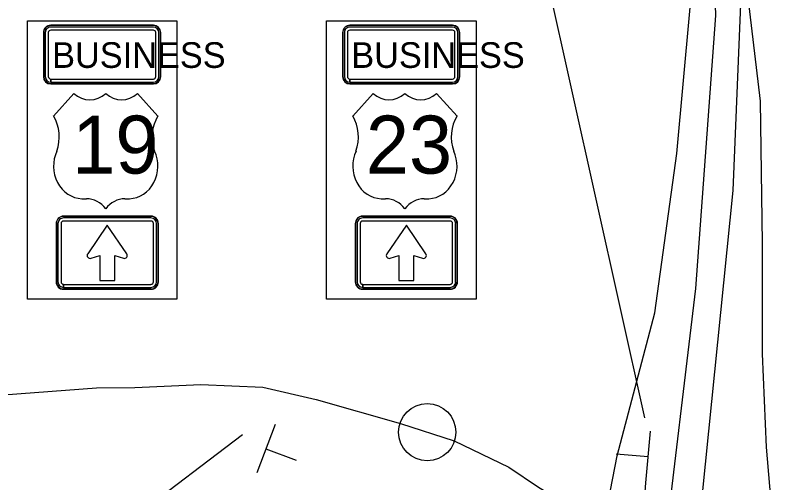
# Model space of a CAD drawing. Extents: x 886234 to 968767, y 455416 to 684046.
# Drawn here: x 914018 to 916508, y 470126 to 471656 of the extents above; entities that cross this region are included whole.
import ezdxf

# ---------------------------------------------------------------- set-up
doc = ezdxf.new("R2010")
doc.units = 0
for name, color, linetype in [('TC DEV SIGN', 7, 'Continuous'), ('TC DEV SIGN BLACK 239', 7, 'Continuous'), ('TC DEV SIGN BLACK ZERO', 7, 'Continuous'), ('TC DEV SIGN WHITE', 7, 'Continuous'), ('TC LABEL TEXT', 7, 'Continuous')]:
    doc.layers.add(name, color=color, linetype=linetype)

msp = doc.modelspace()

# ---------------------------------------------------------------- linework, layer by layer
at = {"layer": 'TC DEV SIGN'}
for p, q in [((914868.7, 470316.7), (914808.4, 470157.9)), ((916083, 470125.8), (916097.8, 470295)), ((914838.6, 470237.3), (914937, 470199.9)), ((916090.4, 470210.4), (915985.5, 470219.6)), ((916068.2, 469956.7), (916083, 470125.8))]:
    msp.add_line(p, q, dxfattribs=at)
at = {"layer": 'TC DEV SIGN BLACK 239'}
for p, q in [((914469.9, 471617), (914133.9, 471617)), ((915449.4, 471617), (915113.4, 471617)), ((914115.9, 471599), (914115.9, 471455)), ((914125.9, 471599), (914125.9, 471455)), ((914469.9, 471607), (914133.9, 471607)), ((914477.9, 471455), (914477.9, 471599)), ((914487.9, 471455), (914487.9, 471599)), ((915095.4, 471599), (915095.4, 471455)), ((915105.4, 471599), (915105.4, 471455)), ((915449.4, 471607), (915113.4, 471607)), ((915457.4, 471455), (915457.4, 471599)), ((915467.4, 471455), (915467.4, 471599)), ((914133.9, 471437), (914133.9, 471447)), ((914134, 471447), (914469.9, 471447)), ((914134, 471447), (914134, 471437)), ((914134, 471437), (914469.9, 471437)), ((915113.4, 471437), (915113.4, 471447)), ((915113.5, 471447), (915449.4, 471447)), ((915113.5, 471447), (915113.5, 471437)), ((915113.5, 471437), (915449.4, 471437)), ((914462.1, 470992.3), (914175.8, 470992.3)), ((915441.6, 470992.3), (915155.3, 470992.3)), ((914157.6, 470974.1), (914157.6, 470783.3)), ((914167.7, 470974.1), (914167.7, 470783.3)), ((914462.1, 470982.2), (914175.8, 470982.2)), ((914470.2, 470783.3), (914470.2, 470974.1)), ((914480.3, 470783.3), (914480.3, 470974.1)), ((915137.1, 470974.1), (915137.1, 470783.3)), ((915147.2, 470974.1), (915147.2, 470783.3)), ((915441.6, 470982.2), (915155.3, 470982.2)), ((915449.7, 470783.3), (915449.7, 470974.1)), ((915459.8, 470783.3), (915459.8, 470974.1)), ((914175.8, 470765), (914175.8, 470775.1)), ((914175.9, 470775.1), (914462.1, 470775.1)), ((914175.9, 470775.1), (914175.9, 470765)), ((914175.9, 470765), (914462.1, 470765)), ((915155.3, 470765), (915155.3, 470775.1)), ((915155.4, 470775.1), (915441.6, 470775.1)), ((915155.4, 470775.1), (915155.4, 470765)), ((915155.4, 470765), (915441.6, 470765))]:
    msp.add_line(p, q, dxfattribs=at)
for points in [[(914383, 470875.3), (914318.9, 470968.6), (914254.9, 470875.3)], [(914383, 470875.3), (914318.9, 470968.6), (914254.9, 470875.3)], [(914383, 470875.3), (914318.9, 470968.6), (914254.9, 470875.3)], [(915362.5, 470875.3), (915298.4, 470968.6), (915234.4, 470875.3)], [(915362.5, 470875.3), (915298.4, 470968.6), (915234.4, 470875.3)], [(915362.5, 470875.3), (915298.4, 470968.6), (915234.4, 470875.3)], [(914265.9, 470860.5), (914294.6, 470869.5), (914294.6, 470787.7), (914343.3, 470787.7)], [(914265.9, 470860.5), (914294.6, 470869.5), (914294.6, 470787.7), (914343.3, 470787.7)], [(914265.9, 470860.5), (914294.6, 470869.5), (914294.6, 470787.7), (914343.3, 470787.7)], [(914343.3, 470787.7), (914343.3, 470869.5), (914372, 470860.5)], [(914343.3, 470787.7), (914343.3, 470869.5), (914372, 470860.5)], [(914343.3, 470787.7), (914343.3, 470869.5), (914372, 470860.5)], [(915245.4, 470860.5), (915274.1, 470869.5), (915274.1, 470787.7), (915322.8, 470787.7)], [(915245.4, 470860.5), (915274.1, 470869.5), (915274.1, 470787.7), (915322.8, 470787.7)], [(915245.4, 470860.5), (915274.1, 470869.5), (915274.1, 470787.7), (915322.8, 470787.7)], [(915322.8, 470787.7), (915322.8, 470869.5), (915351.5, 470860.5)], [(915322.8, 470787.7), (915322.8, 470869.5), (915351.5, 470860.5)], [(915322.8, 470787.7), (915322.8, 470869.5), (915351.5, 470860.5)]]:
    msp.add_lwpolyline(points, dxfattribs=at)
for centre, start, end in [((914262.9, 470869.7), 145.5508, 287.601), ((914262.9, 470869.7), 145.5508, 287.601), ((914262.9, 470869.7), 145.5508, 287.601), ((914374.9, 470869.7), 252.399, 34.4492), ((914374.9, 470869.7), 252.399, 34.4492), ((914374.9, 470869.7), 252.399, 34.4492), ((915242.5, 470869.7), 145.5508, 287.601), ((915242.5, 470869.7), 145.5508, 287.601), ((915242.5, 470869.7), 145.5508, 287.601), ((915354.4, 470869.7), 252.399, 34.4492), ((915354.4, 470869.7), 252.399, 34.4492), ((915354.4, 470869.7), 252.399, 34.4492)]:
    msp.add_arc(centre, 9.74, start, end, dxfattribs=at)
for centre, major_axis, start_param, end_param in [((914133.9, 471599), (18, 0), 1.570796, 3.141593), ((914469.9, 471599), (18, 0), 0, 1.570796), ((915113.4, 471599), (18, 0), 1.570796, 3.141593), ((915449.4, 471599), (18, 0), 0, 1.570796), ((914133.9, 471599), (8, 0), 1.570796, 3.141593), ((914469.9, 471599), (8, 0), 0, 1.570796), ((915113.4, 471599), (8, 0), 1.570796, 3.141593), ((915449.4, 471599), (8, 0), 0, 1.570796), ((914133.9, 471455), (18, 0), 3.141593, 4.712389), ((914133.9, 471455), (8, 0), 3.141593, 4.712389), ((914469.9, 471455), (18, 0), 4.712389, 6.283185), ((914469.9, 471455), (8, 0), 4.712389, 6.283185), ((915113.4, 471455), (18, 0), 3.141593, 4.712389), ((915113.4, 471455), (8, 0), 3.141593, 4.712389), ((915449.4, 471455), (18, 0), 4.712389, 6.283185), ((915449.4, 471455), (8, 0), 4.712389, 6.283185), ((914175.8, 470974.1), (18.3, 0), 1.570796, 3.141593), ((914462.1, 470974.1), (18.3, 0), 0, 1.570796), ((915155.3, 470974.1), (18.3, 0), 1.570796, 3.141593), ((915441.6, 470974.1), (18.3, 0), 0, 1.570796), ((914175.8, 470974.1), (8.11, 0), 1.570796, 3.141593), ((914462.1, 470974.1), (8.11, 0), 0, 1.570796), ((915155.3, 470974.1), (8.11, 0), 1.570796, 3.141593), ((915441.6, 470974.1), (8.11, 0), 0, 1.570796), ((914175.8, 470783.3), (18.3, 0), 3.141593, 4.712389), ((914175.8, 470783.3), (8.11, 0), 3.141593, 4.712389), ((914462.1, 470783.3), (18.3, 0), 4.712389, 6.283185), ((914462.1, 470783.3), (8.11, 0), 4.712389, 6.283185), ((915155.3, 470783.3), (18.3, 0), 3.141593, 4.712389), ((915155.3, 470783.3), (8.11, 0), 3.141593, 4.712389), ((915441.6, 470783.3), (18.3, 0), 4.712389, 6.283185), ((915441.6, 470783.3), (8.11, 0), 4.712389, 6.283185)]:
    msp.add_ellipse(centre, major_axis=major_axis, ratio=0.999865, start_param=start_param, end_param=end_param, dxfattribs=at)
at = {"layer": 'TC DEV SIGN BLACK ZERO'}
for p, q in [((914469.9, 471623), (914133.9, 471623)), ((914133.9, 471622), (914133.9, 471622)), ((914469.9, 471622), (914133.9, 471622)), ((914469.9, 471622), (914469.9, 471622)), ((915449.4, 471623), (915113.4, 471623)), ((915113.4, 471622), (915113.4, 471622)), ((915449.4, 471622), (915113.4, 471622)), ((915449.4, 471622), (915449.4, 471622)), ((914109.9, 471599), (914109.9, 471455)), ((914110.9, 471599), (914110.9, 471455)), ((914110.9, 471599), (914110.9, 471599)), ((914492.9, 471599), (914492.9, 471599)), ((914492.9, 471455), (914492.9, 471599)), ((914493.9, 471455), (914493.9, 471599)), ((915089.4, 471599), (915089.4, 471455)), ((915090.4, 471599), (915090.4, 471455)), ((915090.4, 471599), (915090.4, 471599)), ((915472.4, 471599), (915472.4, 471599)), ((915472.4, 471455), (915472.4, 471599)), ((915473.4, 471455), (915473.4, 471599)), ((914110.9, 471455), (914110.9, 471455)), ((914492.9, 471455), (914492.9, 471455)), ((915090.4, 471455), (915090.4, 471455)), ((915472.4, 471455), (915472.4, 471455)), ((914133.9, 471431), (914133.9, 471432)), ((914133.9, 471432), (914133.9, 471432)), ((914133.9, 471432), (914469.9, 471432)), ((914133.9, 471432), (914133.9, 471431)), ((914133.9, 471431), (914469.9, 471431)), ((914469.9, 471432), (914469.9, 471432)), ((915113.4, 471431), (915113.4, 471432)), ((915113.4, 471432), (915113.4, 471432)), ((915113.4, 471432), (915449.4, 471432)), ((915113.4, 471432), (915113.4, 471431)), ((915113.4, 471431), (915449.4, 471431)), ((915449.4, 471432), (915449.4, 471432)), ((914143.2, 471326), (914210, 471399.8)), ((914143.2, 471326), (914210, 471399.8)), ((914418, 471399.8), (914484.8, 471326)), ((914418, 471399.8), (914484.8, 471326)), ((915122.7, 471326), (915189.5, 471399.8)), ((915122.7, 471326), (915189.5, 471399.8)), ((915397.5, 471399.8), (915464.3, 471326)), ((915397.5, 471399.8), (915464.3, 471326)), ((914462.1, 470998.4), (914175.8, 470998.4)), ((914175.8, 470997.4), (914175.8, 470997.4)), ((914462.1, 470997.4), (914175.8, 470997.4)), ((914462.1, 470997.4), (914462.1, 470997.4)), ((915441.6, 470998.4), (915155.3, 470998.4)), ((915155.3, 470997.4), (915155.3, 470997.4)), ((915441.6, 470997.4), (915155.3, 470997.4)), ((915441.6, 470997.4), (915441.6, 470997.4)), ((914151.5, 470974.1), (914151.5, 470783.3)), ((914152.5, 470974.1), (914152.5, 470783.3)), ((914152.5, 470974.1), (914152.5, 470974.1)), ((914485.4, 470974.1), (914485.4, 470974.1)), ((914485.4, 470783.3), (914485.4, 470974.1)), ((914486.4, 470783.3), (914486.4, 470974.1)), ((915131, 470974.1), (915131, 470783.3)), ((915132, 470974.1), (915132, 470783.3)), ((915132, 470974.1), (915132, 470974.1)), ((915464.9, 470974.1), (915464.9, 470974.1)), ((915464.9, 470783.3), (915464.9, 470974.1)), ((915465.9, 470783.3), (915465.9, 470974.1)), ((914152.5, 470783.3), (914152.5, 470783.3)), ((914485.4, 470783.3), (914485.4, 470783.3)), ((915132, 470783.3), (915132, 470783.3)), ((915464.9, 470783.3), (915464.9, 470783.3)), ((914175.8, 470758.9), (914175.8, 470759.9)), ((914175.8, 470759.9), (914175.8, 470759.9)), ((914175.8, 470759.9), (914462.1, 470759.9)), ((914175.8, 470759.9), (914175.8, 470758.9)), ((914175.8, 470758.9), (914462.1, 470758.9)), ((914462.1, 470759.9), (914462.1, 470759.9)), ((915155.3, 470758.9), (915155.3, 470759.9)), ((915155.3, 470759.9), (915155.3, 470759.9)), ((915155.4, 470759.9), (915441.6, 470759.9)), ((915155.4, 470759.9), (915155.4, 470758.9)), ((915155.4, 470758.9), (915441.6, 470758.9)), ((915441.6, 470759.9), (915441.6, 470759.9))]:
    msp.add_line(p, q, dxfattribs=at)
for centre, major_axis, ratio, start_param, end_param in [((914133.9, 471599), (24, 0), 0.999865, 1.570796, 3.141593), ((914133.9, 471599), (23, 0), 0.999865, 1.570796, 3.141593), ((914469.9, 471599), (24, 0), 0.999865, 0, 1.570796), ((914469.9, 471599), (23, 0), 0.999865, 0, 1.570796), ((915113.4, 471599), (24, 0), 0.999865, 1.570796, 3.141593), ((915113.4, 471599), (23, 0), 0.999865, 1.570796, 3.141593), ((915449.4, 471599), (24, 0), 0.999865, 0, 1.570796), ((915449.4, 471599), (23, 0), 0.999865, 0, 1.570796), ((914133.9, 471455), (24, 0), 0.999865, 3.141593, 4.712389), ((914133.9, 471455), (23, 0), 0.999865, 3.141593, 4.712389), ((914469.9, 471455), (24, 0), 0.999865, 4.712389, 6.283185), ((914469.9, 471455), (23, 0), 0.999865, 4.712389, 6.283185), ((915113.4, 471455), (24, 0), 0.999865, 3.141593, 4.712389), ((915113.4, 471455), (23, 0), 0.999865, 3.141593, 4.712389), ((915449.4, 471455), (24, 0), 0.999865, 4.712389, 6.283185), ((915449.4, 471455), (23, 0), 0.999865, 4.712389, 6.283185), ((914262, 471469.4), (0, -90.2), 0.905624, 5.593452, 6.972919), ((914262, 471469.4), (0, -90.2), 0.905624, 5.593452, 6.972919), ((914366, 471469.4), (0, -90.2), 0.905624, 5.593452, 6.972919), ((914366, 471469.4), (0, -90.2), 0.905624, 5.593452, 6.972919), ((915241.5, 471469.4), (0, -90.2), 0.905624, 5.593452, 6.972919), ((915241.5, 471469.4), (0, -90.2), 0.905624, 5.593452, 6.972919), ((915345.5, 471469.4), (0, -90.2), 0.905624, 5.593452, 6.972919), ((915345.5, 471469.4), (0, -90.2), 0.905624, 5.593452, 6.972919), ((914050.6, 471257.6), (0, -123), 0.905624, 1.184601, 2.161129), ((914050.6, 471257.6), (0, -123), 0.905624, 1.184601, 2.161129), ((914577.3, 471257.6), (0, -123), 0.905624, 4.122057, 5.098584), ((914577.3, 471257.6), (0, -123), 0.905624, 4.122057, 5.098584), ((915030.1, 471257.6), (0, -123), 0.905624, 1.184601, 2.161129), ((915030.2, 471257.6), (0, -123), 0.905624, 1.184601, 2.161129), ((915556.9, 471257.6), (0, -123), 0.905624, 4.122057, 5.098584), ((915556.9, 471257.6), (0, -123), 0.905624, 4.122057, 5.098584), ((914239.7, 471162), (0, 106.6), 0.905624, 1.091068, 3.104197), ((914239.7, 471162), (0, 106.6), 0.905624, 1.091068, 3.104197), ((914388.3, 471162), (0, 106.6), 0.905624, 3.178989, 5.192118), ((914388.3, 471162), (0, 106.6), 0.905624, 3.178989, 5.192118), ((915219.2, 471162), (0, 106.6), 0.905624, 1.091068, 3.104197), ((915219.2, 471162), (0, 106.6), 0.905624, 1.091068, 3.104197), ((915367.8, 471162), (0, 106.6), 0.905624, 3.178989, 5.192118), ((915367.8, 471162), (0, 106.6), 0.905624, 3.178989, 5.192118), ((914251, 470965.2), (0, 90.2), 0.905624, 5.402164, 6.283185), ((914251, 470965.2), (0, 90.2), 0.905624, 5.402164, 6.283185), ((914377, 470965.2), (0, -90.2), 0.905624, 3.141593, 4.022614), ((914377, 470965.2), (0, -90.2), 0.905624, 3.141593, 4.022614), ((915230.5, 470965.2), (0, 90.2), 0.905624, 5.402164, 6.283185), ((915230.5, 470965.2), (0, 90.2), 0.905624, 5.402164, 6.283185), ((915356.5, 470965.2), (0, -90.2), 0.905624, 3.141593, 4.022614), ((915356.5, 470965.2), (0, -90.2), 0.905624, 3.141593, 4.022614), ((914175.8, 470974.1), (24.3, 0), 0.999865, 1.570796, 3.141593), ((914175.8, 470974.1), (23.3, 0), 0.999865, 1.570796, 3.141593), ((914462.1, 470974.1), (24.3, 0), 0.999865, 0, 1.570796), ((914462.1, 470974.1), (23.3, 0), 0.999865, 0, 1.570796), ((915155.3, 470974.1), (24.3, 0), 0.999865, 1.570796, 3.141593), ((915155.3, 470974.1), (23.3, 0), 0.999865, 1.570796, 3.141593), ((915441.6, 470974.1), (24.3, 0), 0.999865, 0, 1.570796), ((915441.6, 470974.1), (23.3, 0), 0.999865, 0, 1.570796), ((914175.8, 470783.3), (24.3, 0), 0.999865, 3.141593, 4.712389), ((914175.8, 470783.3), (23.3, 0), 0.999865, 3.141593, 4.712389), ((914462.1, 470783.3), (24.3, 0), 0.999865, 4.712389, 6.283185), ((914462.1, 470783.3), (23.3, 0), 0.999865, 4.712389, 6.283185), ((915155.3, 470783.3), (24.3, 0), 0.999865, 3.141593, 4.712389), ((915155.3, 470783.3), (23.3, 0), 0.999865, 3.141593, 4.712389), ((915441.6, 470783.3), (24.3, 0), 0.999865, 4.712389, 6.283185), ((915441.6, 470783.3), (23.3, 0), 0.999865, 4.712389, 6.283185)]:
    msp.add_ellipse(centre, major_axis=major_axis, ratio=ratio, start_param=start_param, end_param=end_param, dxfattribs=at)
at = {"layer": 'TC DEV SIGN WHITE'}
for p, q in [((914469.9, 471623), (914133.9, 471623)), ((915449.4, 471623), (915113.4, 471623)), ((914109.9, 471599), (914109.9, 471455)), ((914493.9, 471455), (914493.9, 471599)), ((915089.4, 471599), (915089.4, 471455)), ((915473.4, 471455), (915473.4, 471599)), ((914133.9, 471431), (914469.9, 471431)), ((915113.4, 471431), (915449.4, 471431)), ((914210, 471399.8), (914143.2, 471326)), ((914314, 471399.8), (914314, 471399.8)), ((914484.8, 471326), (914418, 471399.8)), ((915189.5, 471399.8), (915122.7, 471326)), ((915293.5, 471399.8), (915293.5, 471399.8)), ((915464.3, 471326), (915397.5, 471399.8)), ((914153.8, 471211.2), (914154.1, 471211.2)), ((915133.3, 471211.2), (915133.6, 471211.2)), ((914236.1, 471055.5), (914251, 471055.4)), ((914377, 471055.4), (914391.9, 471055.5)), ((915215.6, 471055.5), (915230.5, 471055.4)), ((915356.5, 471055.4), (915371.4, 471055.5)), ((914314, 471022.6), (914314, 471022.6)), ((915293.5, 471022.6), (915293.5, 471022.6)), ((914462.1, 470998.4), (914175.8, 470998.4)), ((915441.6, 470998.4), (915155.3, 470998.4)), ((914151.5, 470974.1), (914151.5, 470783.3)), ((914486.4, 470783.3), (914486.4, 470974.1)), ((915131, 470974.1), (915131, 470783.3)), ((915465.9, 470783.3), (915465.9, 470974.1)), ((914175.8, 470758.9), (914462.1, 470758.9)), ((915155.3, 470758.9), (915441.6, 470758.9))]:
    msp.add_line(p, q, dxfattribs=at)
for points in [[(914473.9, 471211.2), (914474.2, 471211.2)], [(915453.4, 471211.2), (915453.7, 471211.2)]]:
    msp.add_lwpolyline(points, dxfattribs=at)
for centre, major_axis, ratio, start_param, end_param in [((914133.9, 471599), (24, 0), 0.999865, 1.570796, 3.141593), ((914469.9, 471599), (24, 0), 0.999865, 0, 1.570796), ((915113.4, 471599), (24, 0), 0.999865, 1.570796, 3.141593), ((915449.4, 471599), (24, 0), 0.999865, 0, 1.570796), ((914133.9, 471455), (24, 0), 0.999865, 3.141593, 4.712389), ((914469.9, 471455), (24, 0), 0.999865, 4.712389, 6.283185), ((915113.4, 471455), (24, 0), 0.999865, 3.141593, 4.712389), ((915449.4, 471455), (24, 0), 0.999865, 4.712389, 6.283185), ((914262, 471469.4), (0, -90.2), 0.905624, 5.593452, 6.972919), ((914366, 471469.4), (0, -90.2), 0.905624, 5.593452, 6.972919), ((915241.5, 471469.4), (0, -90.2), 0.905624, 5.593452, 6.972919), ((915345.5, 471469.4), (0, -90.2), 0.905624, 5.593452, 6.972919), ((914050.6, 471257.6), (0, -123), 0.905624, 1.184601, 2.161129), ((914577.3, 471257.6), (0, -123), 0.905624, 4.122057, 5.098584), ((915030.1, 471257.6), (0, -123), 0.905624, 1.184601, 2.161129), ((915556.9, 471257.6), (0, -123), 0.905624, 4.122057, 5.098584), ((914239.7, 471162), (0, 106.6), 0.905624, 1.091068, 3.104197), ((914388.3, 471162), (0, 106.6), 0.905624, 3.178989, 5.192118), ((915219.2, 471162), (0, 106.6), 0.905624, 1.091068, 3.104197), ((915367.8, 471162), (0, 106.6), 0.905624, 3.178989, 5.192118), ((914251, 470965.2), (0, 90.2), 0.905624, 5.402164, 6.283185), ((914377, 470965.2), (0, -90.2), 0.905624, 3.141593, 4.022614), ((915230.5, 470965.2), (0, 90.2), 0.905624, 5.402164, 6.283185), ((915356.5, 470965.2), (0, -90.2), 0.905624, 3.141593, 4.022614), ((914175.8, 470974.1), (24.3, 0), 0.999865, 1.570796, 3.141593), ((914462.1, 470974.1), (24.3, 0), 0.999865, 0, 1.570796), ((915155.3, 470974.1), (24.3, 0), 0.999865, 1.570796, 3.141593), ((915441.6, 470974.1), (24.3, 0), 0.999865, 0, 1.570796), ((914175.8, 470783.3), (24.3, 0), 0.999865, 3.141593, 4.712389), ((914462.1, 470783.3), (24.3, 0), 0.999865, 4.712389, 6.283185), ((915155.3, 470783.3), (24.3, 0), 0.999865, 3.141593, 4.712389), ((915441.6, 470783.3), (24.3, 0), 0.999865, 4.712389, 6.283185)]:
    msp.add_ellipse(centre, major_axis=major_axis, ratio=ratio, start_param=start_param, end_param=end_param, dxfattribs=at)
at = {"layer": 'TC LABEL TEXT'}
for points in [[(915944.3, 469983.5), (915988.5, 470213.5), (916112.2, 470682.3), (916183.5, 471203.2), (916289.2, 472351.4)], [(916289.2, 472351.4), (916310.8, 471655.2), (916244.8, 470761.9), (916138.7, 469877.4)], [(915526.7, 472129.4), (915679.2, 472128.9), (916078, 470338.3)], [(916240.8, 469828), (916258.4, 469992), (916368, 471082.2), (916399.8, 471852.6)], [(916399.8, 471852.6), (916457.1, 471375.1), (916463.5, 470910.3), (916463.5, 470547.5), (916476.2, 470241.9), (916501.6, 469949), (916508, 469745.3)], [(911255.9, 470276.2), (911429, 470420.7), (911573.5, 470488.6), (911805, 470586.2), (911973.5, 470631.3), (912135.4, 470671.4), (912219.9, 470676.6), (912347, 470678.4), (912731.8, 470623.4), (913365.8, 470460.9), (913616.7, 470416), (913877.1, 470406.3), (914283.8, 470436.6), (914409.4, 470437.1), (914625.9, 470447.5), (914828.6, 470438.3), (915003, 470397.9), (915279, 470320), (915454.7, 470262.6), (915634, 470177.3), (915731, 470111.5), (915875.5, 470024.3), (915960.8, 469970.3), (916138.7, 469877.4)], [(913173.5, 469218.6), (913359.8, 469219.2), (914761.7, 470284.2)]]:
    msp.add_lwpolyline(points, dxfattribs=at)
for points in [[(914057.4, 471637.8), (914547.1, 471637.8), (914547.1, 470726.9), (914057.4, 470726.9)], [(915036.9, 471637.8), (915526.7, 471637.8), (915526.7, 470726.9), (915036.9, 470726.9)]]:
    msp.add_lwpolyline(points, close=True, dxfattribs=at)
msp.add_circle((915366.8, 470291.3), 93.8, dxfattribs=at)
msp.add_circle((915366.8, 470291.3), 93.8, dxfattribs=at)

# ---------------------------------------------------------------- texts
at = {"layer": 'TC DEV SIGN BLACK 239'}
for s, height, p in [('BUSINESS', 84, (914138.5, 471483.5)), ('BUSINESS', 84, (915118, 471483.5)), ('19', 189.65, (914204.4, 471137.6)), ('23', 189.65, (915166, 471137.6))]:
    msp.add_text(s, height=height, rotation=360, dxfattribs=at).set_placement(p)

doc.saveas('drawing.dxf')
